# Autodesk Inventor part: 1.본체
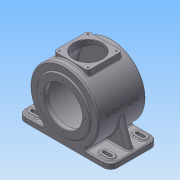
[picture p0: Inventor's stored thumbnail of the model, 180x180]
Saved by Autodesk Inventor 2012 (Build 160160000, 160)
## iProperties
Created: 2015-06
Part Number: 1.본체
Material: 알루미늄-6061
Document SubType Name: Modeling
Designer: Administrator
Density: 2.71 g/cm^3
Mass: 3276.89 g
Surface Area: 2300.02 cm^2
Volume: 1209.18 cm^3
Author: Administrator
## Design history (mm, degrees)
sketch "스케치1"
  geometry: L1 (-115, 59)-(115, 59); L2 (115, 59)-(115, -59); L3 (115, -59)-(-115, -59); L4 (-115, -59)-(-115, 59); 3 further points
  constraints: 8 end point, 2 midpoint, 2 parallel, 1 horizontal, 1 horizontal alignment, 1 perpendicular, 1 vertical alignment
  dimensions: "d0" = 230 distance of L1.start L1.end; "d1" = 118 distance of L1.end L2.end
extrude "돌출1" new body sketch "스케치1" distance "d2" = 14; taper "d3" = 0 deg
fillet "모깎기1" dims "d4" = 18
sketch "스케치2"
  geometry: L1 (-97, 59)-(97, 59) reference; L2 (-97, 50)-(-81, 50); L3 (-81, 32)-(-97, 32); L4 (-97, -32)-(-81, -32); L5 (-81, -50)-(-97, -50); L6 (97, 50)-(81, 50); L7 (81, 32)-(97, 32); L8 (97, -32)-(81, -32); L9 (81, -50)-(97, -50); A1 r 18 centre (-97, 41) between (-97, 59) and (-115, 41) reference; A2 r 18 centre (-97, -41) between (-115, -41) and (-97, -59) reference; A3 r 18 centre (97, -41) between (97, -59) and (115, -41) reference; A4 r 18 centre (97, 41) between (115, 41) and (97, 59) reference; A5 r 9 centre (-97, 41) between (-97, 50) and (-97, 32); A6 r 9 centre (-81, 41) between (-81, 32) and (-81, 50); A7 r 9 centre (97, 41) between (97, 32) and (97, 50); A8 r 9 centre (97, -41) between (97, -50) and (97, -32); A9 r 9 centre (-97, -41) between (-97, -32) and (-97, -50); A10 r 9 centre (-81, -41) between (-81, -50) and (-81, -32); A11 r 9 centre (81, 41) between (81, 50) and (81, 32); A12 r 9 centre (81, -41) between (81, -32) and (81, -50); 1 further point
  constraints: 16 end point, 16 point on circle, 16 tangent, 8 centre point, 5 equal radius, 4 coincident, 4 parallel, 3 equal length, 2 horizontal
  dimensions: "d5" = 9 radius of A5; "d6" = 16 distance of A6.centre A1.centre
extrude "돌출2" join sketch "스케치2" distance "d7" = 3; taper "d8" = 0 deg
sketch "스케치3"
  geometry: L1 (-81, 50)-(-97, 50) reference; L2 (-97, 32)-(-81, 32) reference; L3 (81, 32)-(97, 32) reference; L4 (97, 50)-(81, 50) reference; L5 (97, -32)-(81, -32) reference; L6 (81, -50)-(97, -50) reference; L7 (-81, -32)-(-97, -32) reference; L8 (-97, -50)-(-81, -50) reference; L9 (-97, 37)-(-81, 37); L10 (-81, 45)-(-97, 45); L11 (81, 37)-(97, 37); L12 (97, 45)-(81, 45); L13 (-97, -37)-(-81, -37); L14 (-81, -45)-(-97, -45); L15 (81, -37)-(97, -37); L16 (97, -45)-(81, -45); A1 r 9 centre (-97, 41) between (-97, 50) and (-97, 32) reference; A2 r 9 centre (-81, 41) between (-81, 32) and (-81, 50) reference; A3 r 9 centre (81, 41) between (81, 50) and (81, 32) reference; A4 r 9 centre (97, 41) between (97, 32) and (97, 50) reference; A5 r 9 centre (81, -41) between (81, -32) and (81, -50) reference; A6 r 9 centre (97, -41) between (97, -50) and (97, -32) reference; A7 r 9 centre (-81, -41) between (-81, -50) and (-81, -32) reference; A8 r 9 centre (-97, -41) between (-97, -32) and (-97, -50) reference; A9 r 4 centre (-97, 41) between (-97, 45) and (-97, 37); A10 r 4 centre (-81, 41) between (-81, 37) and (-81, 45); A11 r 4 centre (81, 41) between (81, 45) and (81, 37); A12 r 4 centre (97, 41) between (97, 37) and (97, 45); A13 r 4 centre (-81, -41) between (-81, -45) and (-81, -37); A14 r 4 centre (-97, -41) between (-97, -37) and (-97, -45); A15 r 4 centre (97, -41) between (97, -45) and (97, -37); A16 r 4 centre (81, -41) between (81, -37) and (81, -45); 1 further point
  constraints: 16 end point, 16 point on circle, 8 centre point, 12 other
  dimensions: "d9" = 4 radius of A10; "d10" = 4 radius of A12; "d11" = 4 radius of A13; "d12" = 4 radius of A16
extrude "돌출3" cut sketch "스케치3" stored distance "d13" = 3; taper "d14" = 0 deg
sketch "스케치4"
  geometry: L1 (-97, 0)-(97, 0) reference; C1 r 85 at (0, 85); 2 further points
  constraints: 1 centre point, 1 midpoint, 1 vertical alignment
  dimensions: "d15" = 170 diameter of C1; "d16" = 85 distance from line of L1 C1.centre
extrude "돌출4" join sketch "스케치4" stored distance "d17" = 118; taper "d18" = 0 deg
sketch "스케치5"
  geometry: C1 r 65 at (97, 85); A1 r 85 centre (97, 85) between (143.733, 14) and (50.267, 14) reference; 1 further point
  constraints: 1 centre point, 1 coincident
  dimensions: "d19" = 130 diameter of C1
extrude "돌출5" join sketch "스케치5" distance "d20" = 3; taper "d21" = 0 deg
sketch "스케치6"
  geometry: C1 r 65 at (97, -85); A1 r 85 centre (97, -85) between (50.267, -14) and (143.733, -14) reference; 1 further point
  constraints: 1 centre point, 1 coincident
  dimensions: "d22" = 130 diameter of C1
extrude "돌출6" join sketch "스케치6" distance "d23" = 13; taper "d24" = 0 deg
sketch "스케치7"
  geometry: C1 r 65 at (0, 0) reference; 1 further point
hole "구멍1" sketch "스케치7" at (0, 0) diameter "d25" = 95; stored, may be unused: countersink angle "d29" = 90 deg, drill point angle "d31" = 0 deg; dims "d26" = 6, "d27" = 4, "d28" = 2, "d30" = 11
sketch "스케치8"
  geometry: C1 r 47.5 at (0, 0) reference; 1 further point
hole "구멍2" sketch "스케치8" at (0, 0) diameter "d32" = 154; stored, may be unused: countersink angle "d36" = 90 deg, drill point angle "d38" = 0 deg; dims "d33" = 6, "d34" = 4, "d35" = 2, "d37" = 102
sketch "스케치9"
  geometry: C1 r 77 at (0, 0) reference; C2 r 31 at (0, 0); 1 further point
  constraints: 1 centre point, 1 coincident
  dimensions: "d39" = 62 diameter of C2
extrude "돌출7" join sketch "스케치9" distance "d40" = 3.5; taper "d41" = -25 deg
sketch "스케치10"
  geometry: C1 r 29.368 at (0, 0) reference; 1 further point
hole "구멍3" sketch "스케치10" at (0, 0) diameter "d42" = 30; stored, may be unused: countersink angle "d46" = 90 deg, drill point angle "d48" = 0 deg; dims "d43" = 6, "d44" = 47, "d45" = 14, "d47" = 17
fillet "모깎기2" dims "d49" = 3
chamfer "모따기1" distance "d50" = 1; stored, may be unused: second distance "d51" = 2, angle "d52" = 45 deg
node "작업 평면1"
sketch "스케치11"
  geometry: L1 (-42.5, 42.5)-(42.5, 42.5); L2 (42.5, 42.5)-(42.5, -42.5); L3 (42.5, -42.5)-(-42.5, -42.5); L4 (-42.5, -42.5)-(-42.5, 42.5); 3 further points
  constraints: 8 end point, 2 midpoint, 2 parallel, 1 horizontal, 1 horizontal alignment, 1 perpendicular, 1 vertical alignment
  dimensions: "d54" = 85 distance of L1.start L1.end; "d55" = 85 distance of L1.end L2.end
extrude "돌출8" join sketch "스케치11" stored distance "d56" = 3.5; taper "d57" = 0 deg
sketch "스케치12"
  geometry: 1 further point
hole "구멍4" sketch "스케치12" at (0, 0) diameter "d58" = 70; stored, may be unused: countersink angle "d62" = 90 deg, drill point angle "d64" = 0 deg; dims "d59" = 6, "d60" = 47, "d61" = 14, "d63" = 17
chamfer "모따기2" distance "d65" = 1; stored, may be unused: second distance "d66" = 2, angle "d67" = 45 deg
sketch "스케치13"
  geometry: 1 further point
fillet "모깎기3" dims "d68" = 3
fillet "모깎기4" dims "d69" = 3
fillet "모깎기5" dims "d70" = 7
fillet "모깎기6" dims "d71" = 3
sketch "스케치14"
  geometry: C1 r 36 at (0, 0) reference; 4 further points
  constraints: 2 horizontal alignment, 2 vertical alignment
  dimensions: "d72" = 71 distance of point (35.5, 35.5) point (-35.5, 35.5); "d73" = 71 distance of point (-35.5, 35.5) point (-35.5, -35.5); "d74" = 35.5 horizontal distance of point (-35.5, 35.5) C1.centre; "d75" = 35.5 horizontal distance of C1.centre point (-35.5, 35.5)
hole "구멍5" sketch "스케치14" at (-35.5, 35.5), (-35.5, -35.5), (35.5, -35.5), (35.5, 35.5) diameter "d76" = 3.242; stored, may be unused: countersink angle "d80" = 90 deg, drill point angle "d82" = 118 deg; dims "d77" = 10, "d78" = 47, "d79" = 14, "d81" = 13
sketch "스케치15"
  geometry: C1 r 47.5 at (0, 0) reference; 2 further points
  constraints: 1 vertical alignment
  dimensions: "d83" = 55 distance of C1.centre point (0, 55)
hole "구멍6" sketch "스케치15" at (0, 55) diameter "d84" = 3.242; stored, may be unused: countersink angle "d88" = 90 deg, drill point angle "d90" = 0 deg; dims "d85" = 10, "d86" = 47, "d87" = 14, "d89" = 13
fillet "모깎기7" dims "d94" = 3
chamfer "모따기3" distance "d95" = 1; stored, may be unused: second distance "d96" = 2, angle "d97" = 45 deg
fillet "모깎기8" dims "d98" = 3
sketch "스케치16"
  geometry: L1 (97, 14)-(112, 14) reference; L2 (-112, 14)-(-97, 14) reference; L3 (109, 14)-(84.87, 80.297); L4 (-109, 14)-(-84.87, 80.297); L5 (115, 11)-(115, 0) reference; L6 (-115, 0)-(-115, 11) reference; A1 r 85 centre (0, 85) between (53.953, 19.318) and (-53.953, 19.318) reference; 1 further point
  constraints: 4 end point, 2 point on circle, 2 point on line
  dimensions: "d99" = 110 deg angle of L3 L1; "d100" = 6 distance from line of L3.start L5; "d101" = 110 deg angle of L4 L2; "d102" = 6 distance from line of L4.start L6
feature "리브1" sketch "스케치16" dims "d103" = 1, "d104" = 15, "d105" = 0, "d106" = 0, "d107" = 1, "d108" = 1
fillet "모깎기9" dims "d109" = 7.5
fillet "모깎기10" dims "d110" = 3
node "작업 평면5"
  node "작업 평면4"
sketch "스케치17"
  geometry: 2 further points
  constraints: 1 vertical alignment, 1 other
feature "엠보싱1" sketch "스케치17" dims "d115" = 0.5, "d116" = 0
fillet "모깎기11" dims "d117" = 0.3
node "솔리드1"
pattern_circular "원형 패턴1" dims angle "d92" = 360 deg
mirror "대칭1"
node "작업축3"
other parameters: "d53" = 173, "d113" = 25 deg, "d114" = 85
